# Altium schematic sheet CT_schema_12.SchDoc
size 391 x 278 mm
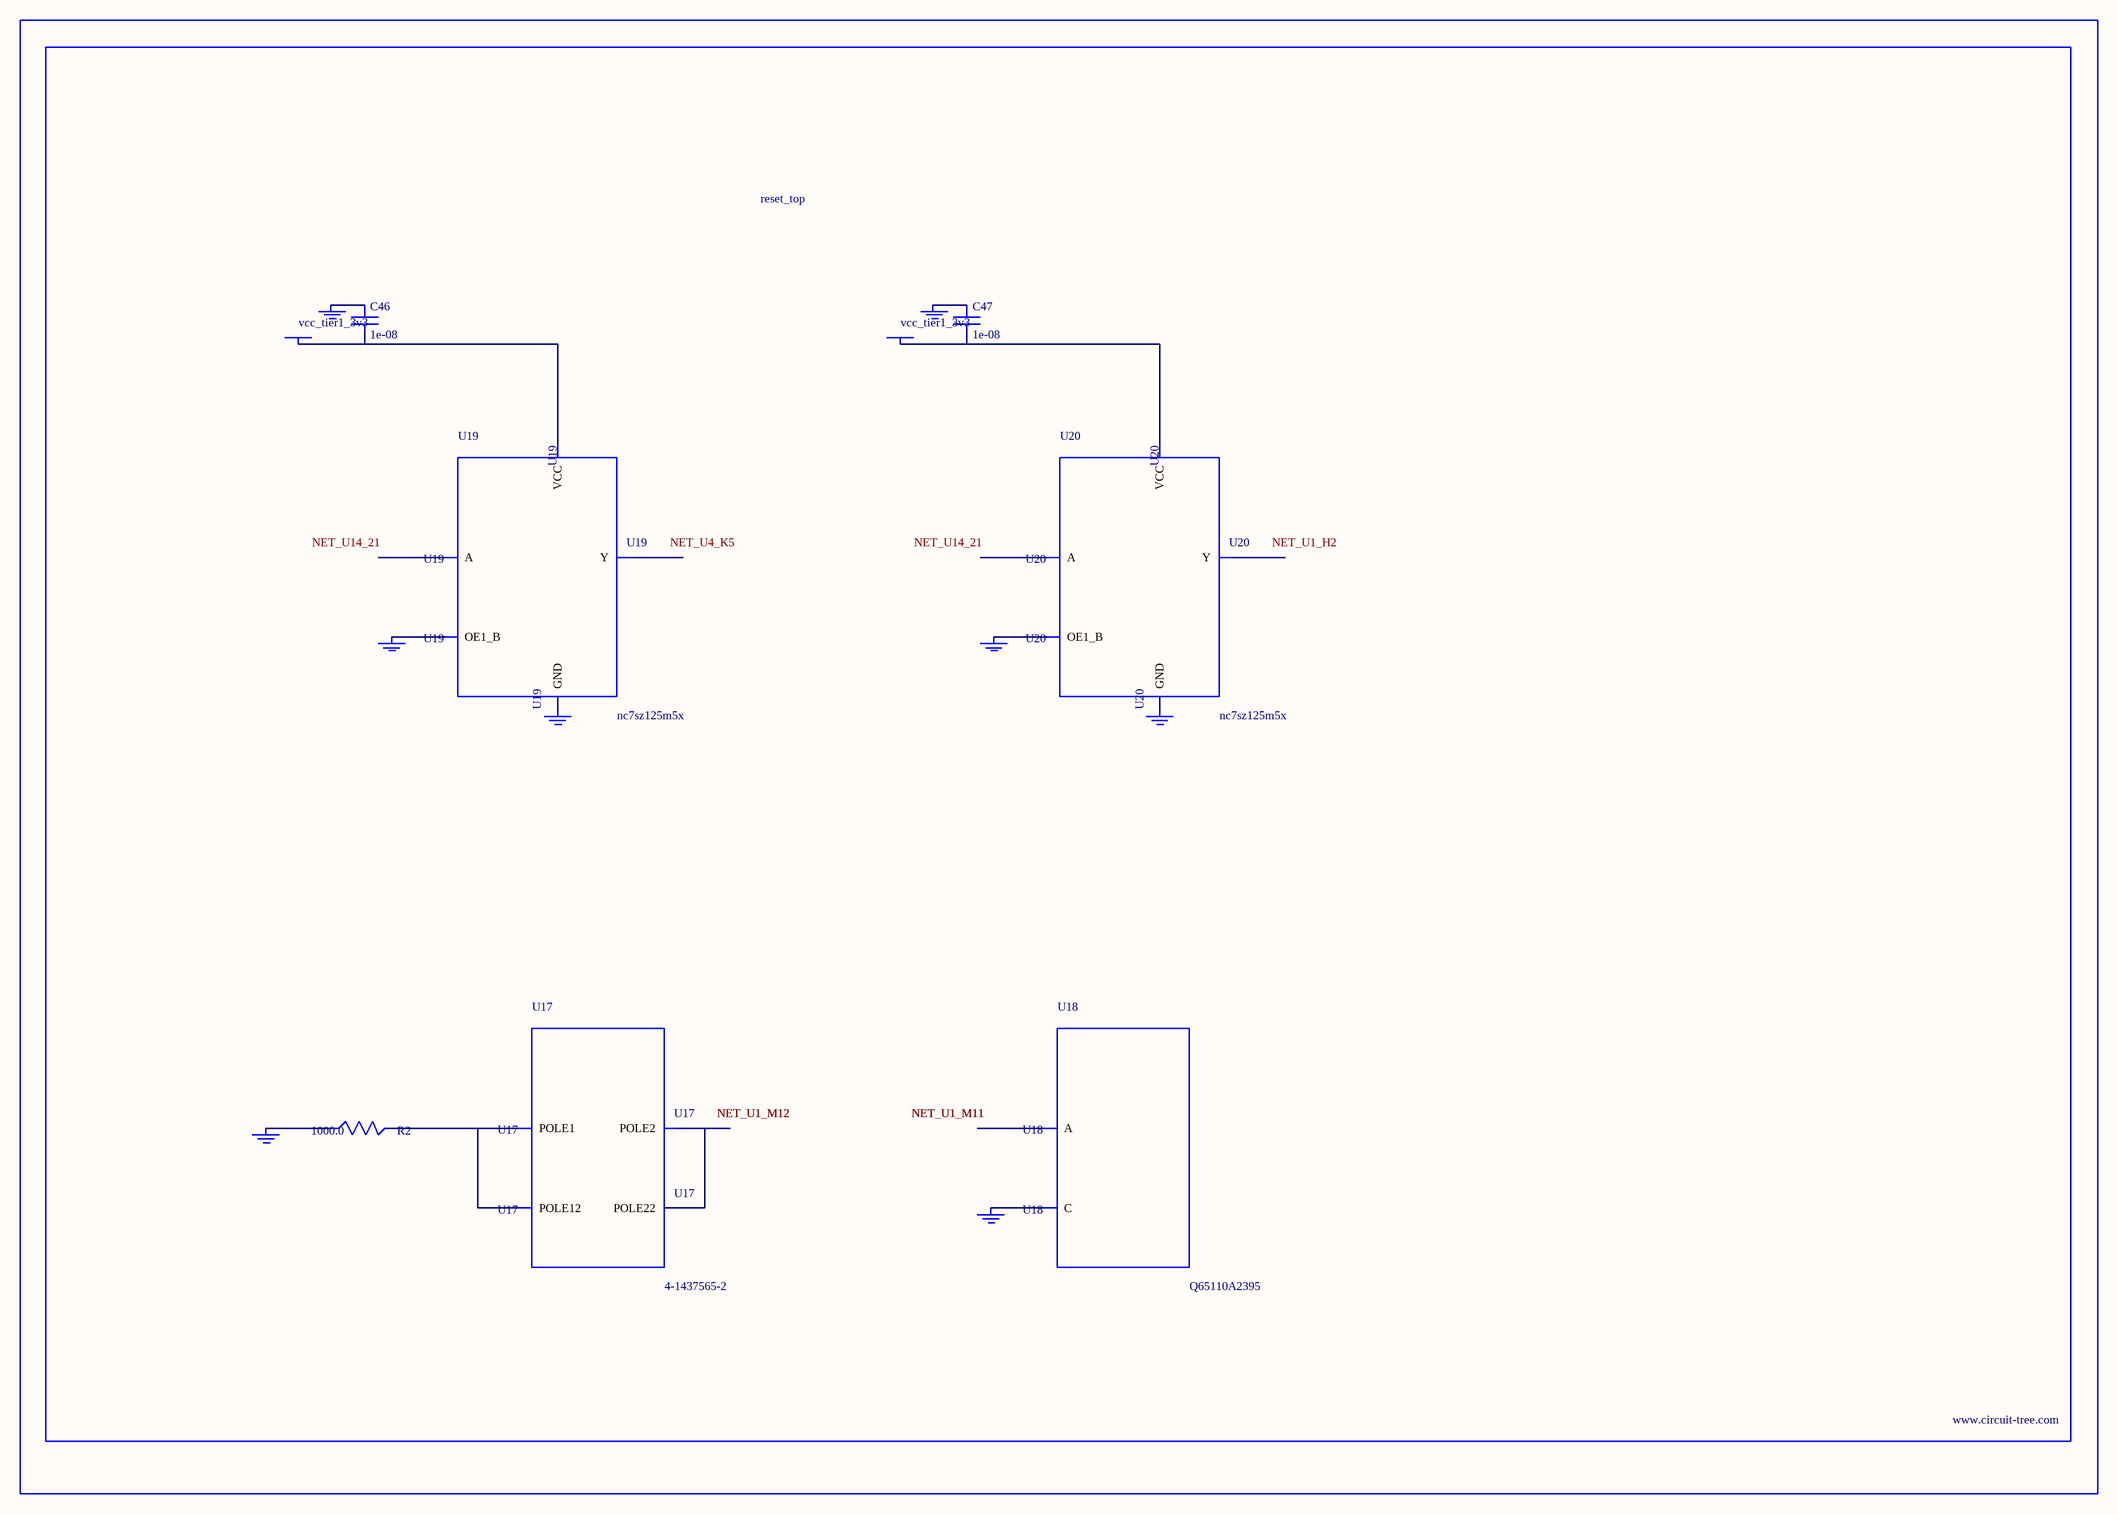
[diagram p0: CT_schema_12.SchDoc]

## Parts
BORDER11  (no value)
C46  1e-08  [C0402]
C47  1e-08  [C0402]
GND_INSTANCE_11_0  (no value)
GND_INSTANCE_11_1  (no value)
GND_INSTANCE_11_2  (no value)
GND_INSTANCE_11_3  (no value)
GND_INSTANCE_11_4  (no value)
GND_INSTANCE_11_5  (no value)
GND_INSTANCE_11_6  (no value)
GND_INSTANCE_11_7  (no value)
POWER_INSTANCE_11_0  vcc_tier1_3v3
POWER_INSTANCE_11_1  vcc_tier1_3v3
R2  1000.0  [R0603]
U17  4-1437565-2  [SW_4-1437565-2]
U18  Q65110A2395  [LGM67K-G1J2-24-Z]
U19  nc7sz125m5x  [NC7SZ125M5X]
U20  nc7sz125m5x  [NC7SZ125M5X]

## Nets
NetC46_1: C46.1 GND_INSTANCE_11_2.0(GND)
NetC46_2: C46.2 POWER_INSTANCE_11_0.0(PWR) U19.5(VCC)
NetC47_1: C47.1 GND_INSTANCE_11_5.0(GND)
NetC47_2: C47.2 POWER_INSTANCE_11_1.0(PWR) U20.5(VCC)
NetGND_INSTANCE_11_0_0: GND_INSTANCE_11_0.0(GND) R2.1
NetGND_INSTANCE_11_1_0: GND_INSTANCE_11_1.0(GND) U18.C
NetGND_INSTANCE_11_3_0: GND_INSTANCE_11_3.0(GND) U19.1(OE1_B)
NetGND_INSTANCE_11_4_0: GND_INSTANCE_11_4.0(GND) U19.3(GND)
NetGND_INSTANCE_11_6_0: GND_INSTANCE_11_6.0(GND) U20.1(OE1_B)
NetGND_INSTANCE_11_7_0: GND_INSTANCE_11_7.0(GND) U20.3(GND)
NetR2_2: R2.2 U17.1(POLE1) U17.2(POLE12)
NetU17_3: U17.3(POLE2) U17.4(POLE22)

Not connected (* = marked no-connect by the designer): U18 A; U19 2(A) 4(Y); U20 2(A) 4(Y)

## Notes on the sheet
- Labels drawn without touching a wire or pin: NET_U1_H2, NET_U4_K5, NET_U14_21

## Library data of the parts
BORDER11 = BORDER_PAGE11
C46 C47 = C0402C103K3RAC
GND_INSTANCE_11_0-GND_INSTANCE_11_7 = GND
POWER_INSTANCE_11_0 POWER_INSTANCE_11_1 = PWR
R2 = RC0603JR-071KL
